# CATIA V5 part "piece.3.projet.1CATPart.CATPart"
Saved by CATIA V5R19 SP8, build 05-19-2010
Part number: piece.3.projet
Bounding box of the stored display mesh (mm): x 0 to 100, y -10 to 10, z -10 to 10
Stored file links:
  F:\piece.3.projet.1CATPart.CATPart
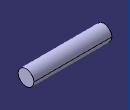
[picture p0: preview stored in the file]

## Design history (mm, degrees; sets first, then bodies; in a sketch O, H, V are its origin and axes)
Parameters
  diametre_p3 = 10 mm
  Longueur_p3 = 100 mm
Body1 (main body)
  Sketch1 on yz-plane, origin (0, 0, 0), H (0, 1, 0), V (0, 0, 1)
    circle A1 centre (0, 0) radius 10
    radius A1 = 10 {= diametre_p3}
  Pad1: profile Sketch1, direction (1, 0, 0), length 100 {= Longueur_p3}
